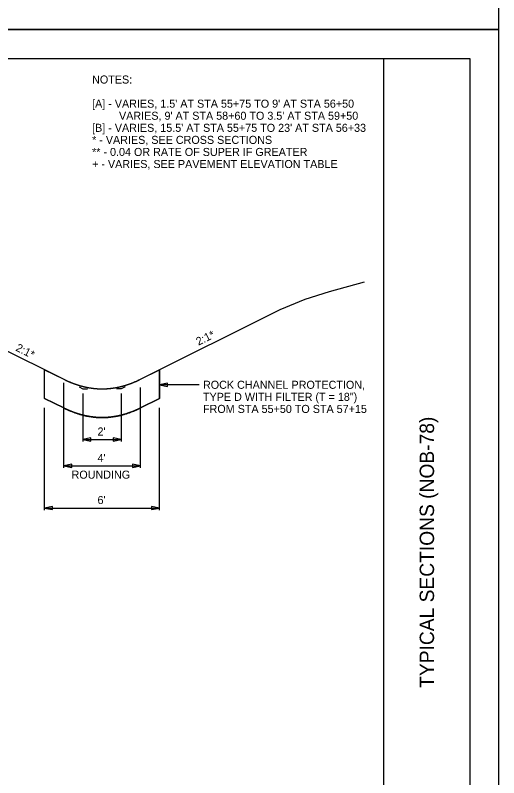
# Model space of a CAD drawing. Extents: x -396 to 156, y -166 to 172.
# Drawn here: x -282.13 to -256.9, y 28.45 to 68.25 of the extents above; entities that cross this region are included whole.
import ezdxf

# ---------------------------------------------------------------- set-up
doc = ezdxf.new("R2010")
doc.units = 0
for name, color, linetype in [('DR_P_Erosion_Control', 7, 'Continuous'), ('DT_X_Terrain_Ground_Line', 7, 'Continuous'), ('SH_Border', 7, 'Continuous'), ('SH_Cut_Line', 7, 'Continuous'), ('SH_Data', 7, 'Continuous'), ('TX_P_1', 7, 'Continuous'), ('TX_X_1', 7, 'Continuous'), ('XS_P_Finished_Grade', 7, 'Continuous')]:
    doc.layers.add(name, color=color, linetype=linetype)

msp = doc.modelspace()

# ---------------------------------------------------------------- linework, layer by layer
at = {"layer": 'DR_P_Erosion_Control'}
for p, q in [((-280.596, 48.254), (-280.596, 49.754)), ((-274.596, 48.254), (-274.596, 49.754)), ((-280.596, 48.254), (-279.596, 47.754)), ((-275.596, 47.754), (-274.596, 48.254))]:
    msp.add_line(p, q, dxfattribs=at)
for points in [[(-279.596, 47.754), (-280.596, 48.254), (-280.596, 49.754), (-279.596, 49.254)], [(-275.596, 49.254), (-274.596, 49.754), (-274.596, 48.254), (-275.596, 47.754)]]:
    msp.add_lwpolyline(points, dxfattribs=at)
for points in [[(-279.596, 49.254), (-279.57, 49.241), (-279.545, 49.229), (-279.519, 49.216), (-279.493, 49.204), (-279.468, 49.192), (-279.442, 49.18), (-279.417, 49.168), (-279.391, 49.157), (-279.365, 49.145), (-279.34, 49.134), (-279.314, 49.123), (-279.288, 49.112), (-279.263, 49.101), (-279.237, 49.091), (-279.211, 49.08), (-279.186, 49.07), (-279.16, 49.06), (-279.134, 49.05), (-279.109, 49.04), (-279.083, 49.031), (-279.057, 49.021), (-279.032, 49.012), (-279.006, 49.003), (-278.981, 48.994), (-278.955, 48.985), (-278.929, 48.976), (-278.904, 48.968), (-278.878, 48.96), (-278.852, 48.951), (-278.827, 48.944), (-278.801, 48.936), (-278.775, 48.928), (-278.75, 48.921), (-278.724, 48.913), (-278.699, 48.906), (-278.673, 48.899), (-278.647, 48.892), (-278.622, 48.886), (-278.596, 48.879), (-278.57, 48.873), (-278.545, 48.867), (-278.519, 48.861), (-278.493, 48.855), (-278.468, 48.849), (-278.442, 48.844), (-278.416, 48.838), (-278.391, 48.833), (-278.365, 48.828), (-278.34, 48.823), (-278.314, 48.819), (-278.288, 48.814), (-278.263, 48.81), (-278.237, 48.805), (-278.211, 48.802), (-278.186, 48.798), (-278.16, 48.794), (-278.134, 48.79), (-278.109, 48.787), (-278.083, 48.784), (-278.057, 48.781), (-278.032, 48.778), (-278.006, 48.775), (-277.981, 48.773), (-277.955, 48.77), (-277.929, 48.768), (-277.904, 48.766), (-277.878, 48.764), (-277.852, 48.762), (-277.827, 48.761), (-277.801, 48.759), (-277.775, 48.758), (-277.75, 48.757), (-277.724, 48.756), (-277.699, 48.755), (-277.673, 48.755), (-277.647, 48.754), (-277.622, 48.754), (-277.596, 48.754), (-277.57, 48.754), (-277.545, 48.754), (-277.519, 48.755), (-277.493, 48.755), (-277.468, 48.756), (-277.442, 48.757), (-277.416, 48.758), (-277.391, 48.759), (-277.365, 48.761), (-277.339, 48.762), (-277.314, 48.764), (-277.288, 48.766), (-277.263, 48.768), (-277.237, 48.77), (-277.211, 48.773), (-277.186, 48.775), (-277.16, 48.778), (-277.134, 48.781), (-277.109, 48.784), (-277.083, 48.787), (-277.057, 48.79), (-277.032, 48.794), (-277.006, 48.798), (-276.981, 48.802), (-276.955, 48.805), (-276.929, 48.81), (-276.904, 48.814), (-276.878, 48.819), (-276.852, 48.823), (-276.827, 48.828), (-276.801, 48.833), (-276.775, 48.838), (-276.75, 48.844), (-276.724, 48.849), (-276.698, 48.855), (-276.673, 48.861), (-276.647, 48.867), (-276.622, 48.873), (-276.596, 48.879), (-276.57, 48.886), (-276.545, 48.892), (-276.519, 48.899), (-276.493, 48.906), (-276.468, 48.913), (-276.442, 48.921), (-276.416, 48.928), (-276.391, 48.936), (-276.365, 48.944), (-276.339, 48.951), (-276.314, 48.96), (-276.288, 48.968), (-276.263, 48.976), (-276.237, 48.985), (-276.211, 48.994), (-276.186, 49.003), (-276.16, 49.012), (-276.134, 49.021), (-276.109, 49.031), (-276.083, 49.04), (-276.057, 49.05), (-276.032, 49.06), (-276.006, 49.07), (-275.981, 49.08), (-275.955, 49.091), (-275.929, 49.101), (-275.904, 49.112), (-275.878, 49.123), (-275.852, 49.134), (-275.827, 49.145), (-275.801, 49.157), (-275.775, 49.168), (-275.75, 49.18), (-275.724, 49.192), (-275.698, 49.204), (-275.673, 49.216), (-275.647, 49.229), (-275.621, 49.241), (-275.596, 49.254)], [(-275.596, 47.754), (-275.621, 47.741), (-275.647, 47.729), (-275.673, 47.716), (-275.698, 47.704), (-275.724, 47.692), (-275.75, 47.68), (-275.775, 47.668), (-275.801, 47.657), (-275.827, 47.645), (-275.852, 47.634), (-275.878, 47.623), (-275.904, 47.612), (-275.929, 47.601), (-275.955, 47.591), (-275.981, 47.58), (-276.006, 47.57), (-276.032, 47.56), (-276.057, 47.55), (-276.083, 47.54), (-276.109, 47.531), (-276.134, 47.521), (-276.16, 47.512), (-276.186, 47.503), (-276.211, 47.494), (-276.237, 47.485), (-276.263, 47.476), (-276.288, 47.468), (-276.314, 47.46), (-276.339, 47.451), (-276.365, 47.444), (-276.391, 47.436), (-276.416, 47.428), (-276.442, 47.421), (-276.468, 47.413), (-276.493, 47.406), (-276.519, 47.399), (-276.545, 47.392), (-276.57, 47.386), (-276.596, 47.379), (-276.622, 47.373), (-276.647, 47.367), (-276.673, 47.361), (-276.698, 47.355), (-276.724, 47.349), (-276.75, 47.344), (-276.775, 47.338), (-276.801, 47.333), (-276.827, 47.328), (-276.852, 47.323), (-276.878, 47.319), (-276.904, 47.314), (-276.929, 47.31), (-276.955, 47.305), (-276.981, 47.302), (-277.006, 47.298), (-277.032, 47.294), (-277.057, 47.29), (-277.083, 47.287), (-277.109, 47.284), (-277.134, 47.281), (-277.16, 47.278), (-277.186, 47.275), (-277.211, 47.273), (-277.237, 47.27), (-277.263, 47.268), (-277.288, 47.266), (-277.314, 47.264), (-277.339, 47.262), (-277.365, 47.261), (-277.391, 47.259), (-277.416, 47.258), (-277.442, 47.257), (-277.468, 47.256), (-277.493, 47.255), (-277.519, 47.255), (-277.545, 47.254), (-277.57, 47.254), (-277.596, 47.254), (-277.622, 47.254), (-277.647, 47.254), (-277.673, 47.255), (-277.699, 47.255), (-277.724, 47.256), (-277.75, 47.257), (-277.775, 47.258), (-277.801, 47.259), (-277.827, 47.261), (-277.852, 47.262), (-277.878, 47.264), (-277.904, 47.266), (-277.929, 47.268), (-277.955, 47.27), (-277.981, 47.273), (-278.006, 47.275), (-278.032, 47.278), (-278.057, 47.281), (-278.083, 47.284), (-278.109, 47.287), (-278.134, 47.29), (-278.16, 47.294), (-278.186, 47.298), (-278.211, 47.302), (-278.237, 47.305), (-278.263, 47.31), (-278.288, 47.314), (-278.314, 47.319), (-278.34, 47.323), (-278.365, 47.328), (-278.391, 47.333), (-278.416, 47.338), (-278.442, 47.344), (-278.468, 47.349), (-278.493, 47.355), (-278.519, 47.361), (-278.545, 47.367), (-278.57, 47.373), (-278.596, 47.379), (-278.622, 47.386), (-278.647, 47.392), (-278.673, 47.399), (-278.699, 47.406), (-278.724, 47.413), (-278.75, 47.421), (-278.775, 47.428), (-278.801, 47.436), (-278.827, 47.444), (-278.852, 47.451), (-278.878, 47.46), (-278.904, 47.468), (-278.929, 47.476), (-278.955, 47.485), (-278.981, 47.494), (-279.006, 47.503), (-279.032, 47.512), (-279.057, 47.521), (-279.083, 47.531), (-279.109, 47.54), (-279.134, 47.55), (-279.16, 47.56), (-279.186, 47.57), (-279.211, 47.58), (-279.237, 47.591), (-279.263, 47.601), (-279.288, 47.612), (-279.314, 47.623), (-279.34, 47.634), (-279.365, 47.645), (-279.391, 47.657), (-279.417, 47.668), (-279.442, 47.68), (-279.468, 47.692), (-279.493, 47.704), (-279.519, 47.716), (-279.545, 47.729), (-279.57, 47.741), (-279.596, 47.754)]]:
    msp.add_open_spline(points, degree=3, dxfattribs=at)
msp.add_spline([(-279.596, 47.754), (-279.519, 47.716), (-279.442, 47.68), (-279.365, 47.645), (-279.288, 47.612), (-279.211, 47.58), (-279.134, 47.55), (-279.057, 47.521), (-278.981, 47.494), (-278.904, 47.468), (-278.827, 47.444), (-278.75, 47.421), (-278.673, 47.399), (-278.596, 47.379), (-278.519, 47.361), (-278.442, 47.344), (-278.365, 47.328), (-278.288, 47.314), (-278.211, 47.302), (-278.134, 47.29), (-278.057, 47.281), (-277.981, 47.273), (-277.904, 47.266), (-277.827, 47.261), (-277.75, 47.257), (-277.673, 47.255), (-277.596, 47.254), (-277.519, 47.255), (-277.442, 47.257), (-277.365, 47.261), (-277.288, 47.266), (-277.211, 47.273), (-277.134, 47.281), (-277.057, 47.29), (-276.981, 47.302), (-276.904, 47.314), (-276.827, 47.328), (-276.75, 47.344), (-276.673, 47.361), (-276.596, 47.379), (-276.519, 47.399), (-276.442, 47.421), (-276.365, 47.444), (-276.288, 47.468), (-276.211, 47.494), (-276.134, 47.521), (-276.057, 47.55), (-275.981, 47.58), (-275.904, 47.612), (-275.827, 47.645), (-275.75, 47.68), (-275.673, 47.716), (-275.596, 47.754)], degree=3, dxfattribs=at)
at = {"layer": 'DT_X_Terrain_Ground_Line'}
msp.add_lwpolyline([(-268.305, 52.9), (-267.006, 53.435), (-265.732, 53.832), (-263.907, 54.337)], dxfattribs=at)
at = {"layer": 'SH_Border'}
msp.add_line((-262.902, 3.004), (-262.902, 66.004), dxfattribs=at)
msp.add_lwpolyline([(-354.402, 66.004), (-258.402, 66.004), (-258.402, 3.004), (-354.402, 3.004)], close=True, dxfattribs=at)
at = {"layer": 'SH_Cut_Line'}
for points in [[(-358.902, 67.504), (-256.902, 67.504), (-256.902, 133.504), (-358.902, 133.504)], [(-358.902, 1.504), (-256.902, 1.504), (-256.902, 67.504), (-358.902, 67.504)]]:
    msp.add_lwpolyline(points, close=True, dxfattribs=at)
at = {"layer": 'TX_P_1'}
for p, q in [((-279.596, 44.637), (-279.596, 49.076)), ((-274.176, 48.882), (-274.176, 49.05)), ((-275.596, 44.637), (-275.596, 48.831)), ((-278.596, 48.516), (-278.596, 46.004)), ((-276.596, 48.516), (-276.596, 46.004)), ((-280.596, 42.417), (-280.596, 47.765)), ((-274.596, 42.417), (-274.596, 47.765)), ((-278.176, 46.023), (-278.176, 46.191)), ((-277.016, 46.191), (-277.016, 46.023)), ((-278.596, 46.107), (-276.596, 46.107)), ((-279.596, 44.731), (-275.596, 44.731)), ((-279.176, 44.647), (-279.176, 44.815)), ((-276.016, 44.815), (-276.016, 44.647)), ((-280.176, 42.448), (-280.176, 42.616)), ((-275.016, 42.616), (-275.016, 42.448)), ((-280.596, 42.532), (-274.596, 42.532))]:
    msp.add_line(p, q, dxfattribs=at)
for points in [[(-274.176, 49.05), (-274.596, 48.966), (-274.176, 48.882)], [(-278.798, 48.855), (-278.596, 48.754), (-278.354, 48.754)], [(-276.393, 48.855), (-276.596, 48.754), (-276.838, 48.754)], [(-278.176, 46.191), (-278.596, 46.107), (-278.176, 46.023)], [(-277.016, 46.023), (-276.596, 46.107), (-277.016, 46.191)], [(-279.176, 44.815), (-279.596, 44.731), (-279.176, 44.647)], [(-276.016, 44.647), (-275.596, 44.731), (-276.016, 44.815)], [(-280.176, 42.616), (-280.596, 42.532), (-280.176, 42.448)], [(-275.016, 42.448), (-274.596, 42.532), (-275.016, 42.616)]]:
    msp.add_lwpolyline(points, dxfattribs=at)
at = {"layer": 'TX_X_1'}
msp.add_line((-272.531, 48.966), (-274.596, 48.966), dxfattribs=at)
at = {"layer": 'XS_P_Finished_Grade'}
for p, q in [((-275.596, 49.254), (-268.305, 52.9)), ((-283.833, 51.373), (-279.596, 49.254))]:
    msp.add_line(p, q, dxfattribs=at)
msp.add_spline([(-279.596, 49.254), (-279.519, 49.216), (-279.442, 49.18), (-279.365, 49.145), (-279.288, 49.112), (-279.211, 49.08), (-279.134, 49.05), (-279.057, 49.021), (-278.981, 48.994), (-278.904, 48.968), (-278.827, 48.944), (-278.75, 48.921), (-278.673, 48.899), (-278.596, 48.879), (-278.519, 48.861), (-278.442, 48.844), (-278.365, 48.828), (-278.288, 48.814), (-278.211, 48.802), (-278.134, 48.79), (-278.057, 48.781), (-277.981, 48.773), (-277.904, 48.766), (-277.827, 48.761), (-277.75, 48.757), (-277.673, 48.755), (-277.596, 48.754), (-277.519, 48.755), (-277.442, 48.757), (-277.365, 48.761), (-277.288, 48.766), (-277.211, 48.773), (-277.134, 48.781), (-277.057, 48.79), (-276.981, 48.802), (-276.904, 48.814), (-276.827, 48.828), (-276.75, 48.844), (-276.673, 48.861), (-276.596, 48.879), (-276.519, 48.899), (-276.442, 48.921), (-276.365, 48.944), (-276.288, 48.968), (-276.211, 48.994), (-276.134, 49.021), (-276.057, 49.05), (-275.981, 49.08), (-275.904, 49.112), (-275.827, 49.145), (-275.75, 49.18), (-275.673, 49.216), (-275.596, 49.254)], degree=3, dxfattribs=at)

# ---------------------------------------------------------------- texts
at = {"layer": 'SH_Data'}
msp.add_text('TYPICAL SECTIONS (NOB-78)', height=0.75, rotation=90, dxfattribs=at).set_placement((-260.277, 33.148))
at = {"layer": 'TX_P_1'}
for rotation, p in [(26.5651, (-272.567, 51.003)), (333.4349, (-282.144, 50.763))]:
    msp.add_text('2:1*', height=0.42, rotation=rotation, dxfattribs=at).set_placement(p)
for s, p in [("2'", (-277.835, 46.317)), ("4'", (-277.835, 44.941)), ('ROUNDING', (-279.19, 44.065)), ("6'", (-277.835, 42.742))]:
    msp.add_text(s, height=0.42, dxfattribs=at).set_placement(p)
at = {"layer": 'TX_X_1'}
for s, p in [('NOTES:', (-278.119, 64.689)), ("[A] - VARIES, 1.5' AT STA 55+75 TO 9' AT STA 56+50", (-278.119, 63.429)), ("         VARIES, 9' AT STA 58+60 TO 3.5' AT STA 59+50", (-278.119, 62.799)), ("[B] - VARIES, 15.5' AT STA 55+75 TO 23' AT STA 56+33", (-278.119, 62.169)), ('* - VARIES, SEE CROSS SECTIONS', (-278.119, 61.539)), ('** - 0.04 OR RATE OF SUPER IF GREATER', (-278.119, 60.909)), ('+ - VARIES, SEE PAVEMENT ELEVATION TABLE', (-278.119, 60.279)), ('ROCK CHANNEL PROTECTION,', (-272.333, 48.756)), ('TYPE D WITH FILTER (T = 18")', (-272.333, 48.126)), ('FROM STA 55+50 TO STA 57+15', (-272.333, 47.496))]:
    msp.add_text(s, height=0.42, dxfattribs=at).set_placement(p)

doc.saveas('drawing.dxf')
